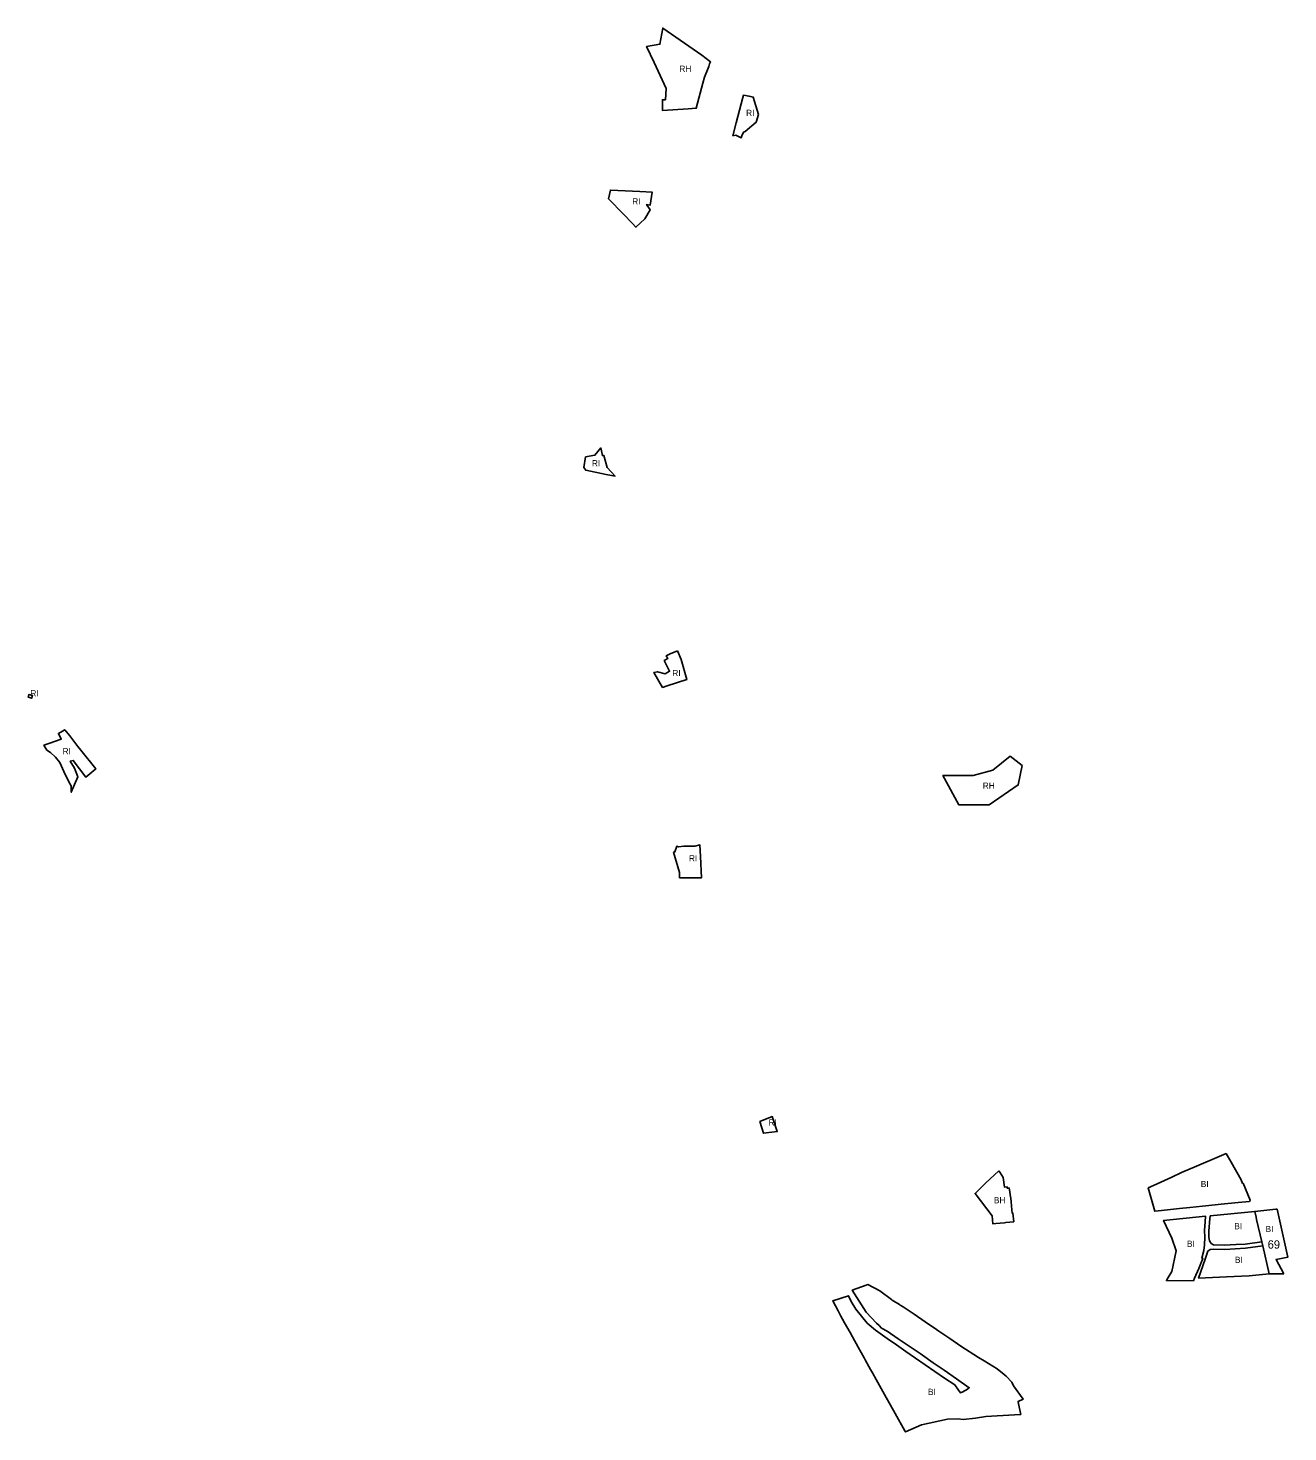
# Model space of a CAD drawing. Extents: x -477010 to -466219, y -1158799 to -1150161.
# Drawn here: x -476385 to -474573, y -1154455 to -1152436 of the extents above; entities that cross this region are included whole.
import ezdxf

# ---------------------------------------------------------------- set-up
doc = ezdxf.new("R2010")
doc.units = 0
for name, color, linetype in [('16', 7, 'Continuous'), ('19', 7, 'Continuous'), ('4', 7, 'Continuous'), ('61', 7, 'Continuous'), ('7', 7, 'Continuous'), ('8', 7, 'Continuous')]:
    doc.layers.add(name, color=color, linetype=linetype)

msp = doc.modelspace()

# ---------------------------------------------------------------- linework, layer by layer
at = {"layer": '16'}
for points in [[(-475405, -1152487.43), (-475406.15, -1152491.07), (-475407.33, -1152493.63), (-475412.33, -1152506.59), (-475414.74, -1152515.33), (-475424.25, -1152551.2), (-475435.79, -1152551.96), (-475472.87, -1152554.39), (-475472.98, -1152538.9), (-475468.64, -1152538.9), (-475467.54, -1152522.6), (-475484.8, -1152485.64), (-475495.59, -1152462.53), (-475476.52, -1152459.12), (-475472.34, -1152435.92), (-475416.43, -1152474.98), (-475403.53, -1152484.59)], [(-474972.6, -1153483.16), (-474955.293, -1153496.532), (-474961.206, -1153524.261), (-475002.816, -1153552.807), (-475046.609, -1153552.807), (-475067.07, -1153514.99), (-475069.36, -1153510.76), (-475026.08, -1153510.65), (-474997.56, -1153502.86)]]:
    msp.add_lwpolyline(points, close=True, dxfattribs=at)
at = {"layer": '19'}
for points in [[(-475371.66, -1152590.85), (-475366.93, -1152572.39), (-475357.37, -1152535.88), (-475356.46, -1152532.42), (-475348.36, -1152533.98), (-475342.38, -1152535.13), (-475334.94, -1152559.97), (-475338.15, -1152571.35), (-475353.68, -1152584.42), (-475356.07, -1152585.41), (-475358.48, -1152590.93), (-475359.79, -1152593.93), (-475367.25, -1152590.05)], [(-475516.03, -1152717.12), (-475528.967, -1152703.654), (-475550.48, -1152681.26), (-475547.68, -1152668.96), (-475505.36, -1152671.17), (-475487.56, -1152672.1), (-475490.41, -1152690.43), (-475495.82, -1152689.6), (-475490.4, -1152697.4), (-475498.36, -1152710.25), (-475510.93, -1152722.23)], [(-475552.27, -1153067.79), (-475540.95, -1153080.1), (-475553.81, -1153077.96), (-475583.32, -1153071.89), (-475585.93, -1153067.62), (-475583.49, -1153052.63), (-475570.02, -1153050.3), (-475561.34, -1153039.56), (-475559.14, -1153050.74), (-475557.12, -1153050.39)], [(-475451.464, -1153331.496), (-475445.774, -1153344.066), (-475437.573, -1153372.78), (-475466.18, -1153382.02), (-475472.61, -1153384), (-475485.262, -1153362.581), (-475480.22, -1153361.56), (-475469.16, -1153364.39), (-475462.72, -1153360.75), (-475470.33, -1153345.4), (-475465.25, -1153342.71), (-475467.44, -1153338.81), (-475461.94, -1153335.73)], [(-476385.37, -1153398), (-476384.15, -1153394.19), (-476378.91, -1153395.87), (-476380.13, -1153399.68)], [(-476346.01, -1153484.15), (-476353.06, -1153477.77), (-476358.49, -1153474.24), (-476362.51, -1153467.22), (-476355.41, -1153464.67), (-476337.699, -1153458.304), (-476341.76, -1153450.186), (-476335.86, -1153446.89), (-476333.64, -1153445.65), (-476332.544, -1153445.038), (-476325.529, -1153453.927), (-476313.72, -1153468.89), (-476309.49, -1153474.25), (-476288.12, -1153501.24), (-476302.48, -1153513.07), (-476320.27, -1153489.18), (-476324.58, -1153490.06), (-476318.75, -1153500.26), (-476313.98, -1153512.84), (-476323.34, -1153534.94), (-476323.23, -1153525.8), (-476325.66, -1153521.55), (-476334.1, -1153505.22), (-476339.53, -1153492.24)], [(-475430.124, -1153657.68), (-475448.138, -1153657.68), (-475448.34, -1153650.42), (-475456.81, -1153620.77), (-475455.01, -1153620.7), (-475452.37, -1153612.38), (-475449.68, -1153613.23), (-475442.1, -1153612.19), (-475426.22, -1153612.36), (-475418.913, -1153610.689), (-475418.082, -1153627.199), (-475416.546, -1153657.68)], [(-475312.66, -1154007.91), (-475311.14, -1154012.48), (-475307.73, -1154022.79), (-475327.77, -1154025.17), (-475332.62, -1154008.15), (-475314.88, -1154001.19)]]:
    msp.add_lwpolyline(points, close=True, dxfattribs=at)
at = {"layer": '4'}
msp.add_lwpolyline([(-474989.024, -1154079.09), (-474987.76, -1154081.13), (-474983, -1154088.81), (-474980.92, -1154102.54), (-474977.2, -1154102.11), (-474976.93, -1154104.39), (-474973.98, -1154104.08), (-474973.35, -1154109.41), (-474972.84, -1154113.68), (-474971.58, -1154118.43), (-474971.1, -1154124.03), (-474970.12, -1154135.38), (-474969.71, -1154140.17), (-474968.75, -1154140.05), (-474967.686, -1154152.572), (-474978.89, -1154153.71), (-474981.12, -1154153.94), (-474993.25, -1154155.18), (-474997.45, -1154155.62), (-474998.43, -1154143.87), (-475023.31, -1154111.7), (-475008.19, -1154096.78)], close=True, dxfattribs=at)
at = {"layer": '7'}
for points in [[(-474628.62, -1154123.46), (-474644.68, -1154125), (-474669.05, -1154127.27), (-474691.44, -1154129.37), (-474696.31, -1154129.91), (-474714.23, -1154131.89), (-474729.21, -1154133.52), (-474754.96, -1154136.37), (-474764.74, -1154137.45), (-474774.01, -1154103.62), (-474766.67, -1154100.27), (-474740.43, -1154088.26), (-474726.05, -1154081.69), (-474704.5, -1154072.57), (-474672.29, -1154058.71), (-474662.15, -1154054.34), (-474654.99, -1154066.66), (-474640.49, -1154092.23), (-474638.54, -1154097.46), (-474637.68, -1154097.11), (-474627.31, -1154121.3)], [(-474709.05, -1154237.51), (-474747.97, -1154237.14), (-474745.38, -1154232.64), (-474740.33, -1154223.86), (-474733.79, -1154194.37), (-474740.17, -1154176.02), (-474752.01, -1154150.58), (-474691.62, -1154144.65), (-474692.18, -1154152.78), (-474693.03, -1154164.95), (-474692.84, -1154174.69), (-474693.37, -1154185.62), (-474694.4, -1154193.76), (-474697.06, -1154204.88), (-474695.55, -1154205.35), (-474701.24, -1154219.56), (-474707.39, -1154233.69)], [(-474684.95, -1154144.05), (-474620.87, -1154137.64), (-474618.84, -1154146.03), (-474618.19, -1154149.22), (-474610.8, -1154181.26), (-474634.91, -1154184.52), (-474647.79, -1154185.34), (-474664.86, -1154186.39), (-474680.09, -1154185.9), (-474683.82, -1154183.55), (-474685.89, -1154180.02), (-474686.81, -1154174.67), (-474686.99, -1154164.98), (-474686.6, -1154160.7), (-474686.04, -1154152.95)], [(-474600.15, -1154227.43), (-474629.14, -1154230.05), (-474661.76, -1154231.63), (-474701.71, -1154233.46), (-474692.35, -1154206.36), (-474688.25, -1154194.79), (-474684.83, -1154192.42), (-474680.03, -1154191.9), (-474664.02, -1154192.28), (-474634.24, -1154190.44), (-474609.45, -1154187.08)], [(-475142.29, -1154265.2), (-475131.83, -1154271.67), (-475130.9, -1154272.25), (-475126.6, -1154274.91), (-475110.8, -1154285.51), (-475095.15, -1154296.38), (-475078.7, -1154307.46), (-475075.36, -1154309.75), (-475059.58, -1154320.43), (-475043.93, -1154331.29), (-475018.21, -1154347.49), (-475010.16, -1154352.72), (-474991.64, -1154363.99), (-474981.53, -1154372.27), (-474978.58, -1154374.69), (-474970.31, -1154383.07), (-474967.8, -1154388.37), (-474954.11, -1154407.68), (-474961.35, -1154410.8), (-474960.51, -1154414.51), (-474957.5, -1154429.59), (-474966.39, -1154430.37), (-475007.64, -1154432.77), (-475022.59, -1154434.88), (-475040.38, -1154436.99), (-475047.63, -1154436.05), (-475062.78, -1154436.2), (-475100.13, -1154444.57), (-475123.41, -1154454.72), (-475124.23, -1154453.27), (-475138.14, -1154428.42), (-475153.57, -1154400.85), (-475165.4, -1154379.46), (-475170.96, -1154369.59), (-475173.42, -1154365.18), (-475181.18, -1154351.19), (-475182.93, -1154348.03), (-475191.5, -1154332.78), (-475199.38, -1154317.86), (-475202.85, -1154311.58), (-475210.89, -1154297.76), (-475213.67, -1154292.61), (-475216.12, -1154288.08), (-475220.13, -1154280.64), (-475227.84, -1154266.36), (-475205.11, -1154258.91), (-475201.45, -1154267.04), (-475194.95, -1154278.35), (-475178.63, -1154298.27), (-475166.46, -1154308.58), (-475149.69, -1154320.47), (-475136.16, -1154329.7), (-475122.85, -1154338.86), (-475067.14, -1154377.25), (-475052.47, -1154386.84), (-475047.03, -1154394.63), (-475044.16, -1154398.73), (-475040.89, -1154396.99), (-475038.58, -1154395.8), (-475035.58, -1154394.25), (-475031.62, -1154391.13), (-475049.97, -1154378.36), (-475067.84, -1154365.92), (-475083.33, -1154355.18), (-475099.03, -1154344.4), (-475102.38, -1154342.03), (-475117.94, -1154331.42), (-475133.75, -1154320.69), (-475149.56, -1154309.96), (-475157.62, -1154305.28), (-475161.3, -1154301.81), (-475165.11, -1154298.21), (-475179.67, -1154282.69), (-475199.76, -1154251.03), (-475179.78, -1154243.74), (-475177.62, -1154242.93), (-475160.41, -1154251.98), (-475143.44, -1154264.49)]]:
    msp.add_lwpolyline(points, close=True, dxfattribs=at)
at = {"layer": '8'}
msp.add_lwpolyline([(-474579.09, -1154227.32), (-474590.17, -1154206.7), (-474573.2, -1154203.29), (-474588.76, -1154134.41), (-474590.47, -1154134.6), (-474620.87, -1154137.64), (-474618.84, -1154146.03), (-474618.19, -1154149.22), (-474610.8, -1154181.26), (-474609.45, -1154187.08), (-474600.15, -1154227.43)], close=True, dxfattribs=at)

# ---------------------------------------------------------------- texts
at = {"layer": '16'}
for p in [(-475448.6165, -1152498.874), (-475012.2385, -1153529.844)]:
    msp.add_text('RH', height=9, dxfattribs=at).set_placement(p)
at = {"layer": '19'}
for p in [(-475352.552, -1152562.447), (-475516.403, -1152689.573), (-475574.4076, -1153066.2727), (-475458.7256, -1153367.8941), (-476382.075, -1153396.93), (-476335.7762, -1153480.2831), (-475434.834, -1153634.326), (-475320.274, -1154014.293)]:
    msp.add_text('RI', height=9, dxfattribs=at).set_placement(p)
at = {"layer": '4'}
msp.add_text('BH', height=9, dxfattribs=at).set_placement((-474996.2291, -1154125.8935))
at = {"layer": '61'}
msp.add_text('69', height=12, dxfattribs=at).set_placement((-474602.384, -1154191.1533))
at = {"layer": '7'}
for p in [(-474698.555, -1154102.657), (-474650.366, -1154163.293), (-474718.396, -1154188.602), (-474649.521, -1154211.702), (-475090.913, -1154401.666)]:
    msp.add_text('BI', height=9, dxfattribs=at).set_placement(p)
at = {"layer": '8'}
msp.add_text('BI', height=9, dxfattribs=at).set_placement((-474605.4309, -1154167.3865))

doc.saveas('drawing.dxf')
